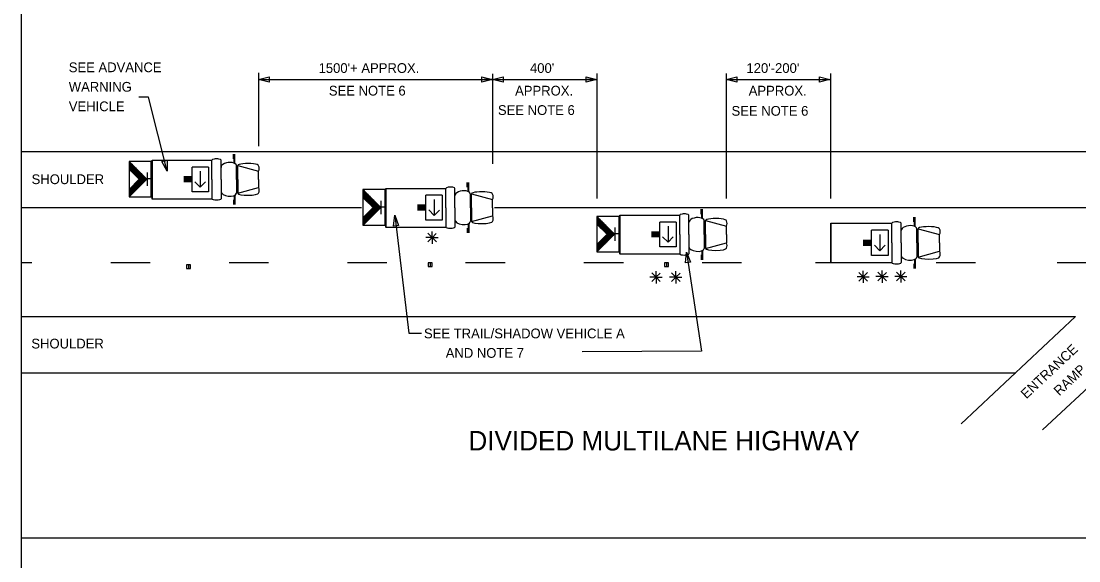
# Model space of a CAD drawing. Extents: x 1807779 to 1818251, y 673292 to 678849.
# Drawn here: x 1816601 to 1817251, y 676712 to 677044 of the extents above; entities that cross this region are included whole.
import ezdxf

# ---------------------------------------------------------------- set-up
doc = ezdxf.new("R2010")
doc.units = 0
for name, color, linetype in [('DSN_DRFT_Guideline-No-Plot', 7, 'Continuous'), ('DSN_RDWY_Drive', 7, 'Continuous'), ('Level 1', 7, 'Continuous')]:
    doc.layers.add(name, color=color, linetype=linetype)

msp = doc.modelspace()

# ---------------------------------------------------------------- linework, layer by layer
at = {"layer": 'DSN_DRFT_Guideline-No-Plot'}
msp.add_lwpolyline([(1816600.63, 676379.88), (1818250.63, 676379.88), (1818250.63, 677429.88), (1816600.63, 677429.88)], close=True, dxfattribs=at)
at = {"layer": 'DSN_RDWY_Drive'}
for p, q in [((1816746.7, 677012.14), (1816746.7, 676967.16)), ((1816746.7, 677008.08), (1816752.26, 677008.08)), ((1816746.7, 677008.08), (1816890.57, 677008.08)), ((1816890.57, 677008.08), (1816885.28, 677008.08)), ((1816890.57, 677011.54), (1816890.57, 676956.09)), ((1816890.57, 677008.08), (1816896.75, 677008.08)), ((1816890.57, 677008.08), (1816954.71, 677008.08)), ((1816953.98, 677008.08), (1816948.69, 677008.08)), ((1816954.71, 677011.78), (1816954.71, 676934.89)), ((1817034.25, 677011.78), (1817034.25, 676934.89)), ((1817034.25, 677008.08), (1817040.43, 677008.08)), ((1817034.25, 677008.08), (1817098.39, 677008.08)), ((1817098.39, 677011.78), (1817098.39, 676934.89)), ((1816600.9, 676963.87), (1817400.95, 676963.87)), ((1816731.21, 676959.21), (1816731.21, 676962.12)), ((1816731.67, 676956.41), (1816731.67, 676962.12)), ((1816732.06, 676956.41), (1816732.06, 676962.12)), ((1816666.98, 676957.72), (1816677.93, 676946.78)), ((1816681.08, 676958.23), (1816681.08, 676934.46)), ((1816681.18, 676934.73), (1816681.18, 676958.5)), ((1816681.18, 676958.5), (1816681.18, 676934.73)), ((1816681.18, 676958.5), (1816717.97, 676958.5)), ((1816715.81, 676954.22), (1816705.76, 676954.22)), ((1816705.76, 676939), (1816705.76, 676954.22)), ((1816715.81, 676954.22), (1816715.81, 676939)), ((1816717.97, 676946.61), (1816717.97, 676958.5)), ((1816723.61, 676946.61), (1816723.61, 676958.5)), ((1816733.05, 676946.61), (1816733.05, 676955.17)), ((1816733.84, 676955.17), (1816746.7, 676951.66)), ((1816733.84, 676946.61), (1816733.84, 676955.17)), ((1816666.98, 676952.97), (1816673.26, 676946.71)), ((1816678.3, 676942.65), (1816678.3, 676950.9)), ((1816705.76, 676948.13), (1816700.63, 676948.13)), ((1816705.76, 676947.37), (1816700.63, 676947.37)), ((1816710.78, 676951.64), (1816710.78, 676941.9)), ((1816746.7, 676946.61), (1816746.7, 676951.66)), ((1816666.98, 676940.44), (1816673.26, 676946.71)), ((1816667.04, 676935.87), (1816677.93, 676946.78)), ((1816680.59, 676946.97), (1816678.24, 676946.97)), ((1816705.76, 676946.61), (1816700.63, 676946.61)), ((1816705.76, 676945.85), (1816700.63, 676945.85)), ((1816705.76, 676945.09), (1816700.63, 676945.09)), ((1816710.78, 676941.9), (1816707.48, 676945.21)), ((1816710.78, 676941.9), (1816714.01, 676945.13)), ((1816717.97, 676946.61), (1816717.97, 676934.73)), ((1816723.61, 676946.61), (1816723.61, 676934.73)), ((1816733.05, 676946.61), (1816733.05, 676938.05)), ((1816733.84, 676946.61), (1816733.84, 676938.05)), ((1816733.84, 676938.05), (1816746.7, 676941.57)), ((1816746.7, 676946.61), (1816746.7, 676941.57)), ((1816824.95, 676940.81), (1816824.95, 676917.04)), ((1816825.04, 676941.09), (1816825.04, 676917.32)), ((1816825.04, 676917.31), (1816825.04, 676941.08)), ((1816825.04, 676941.08), (1816861.84, 676941.08)), ((1816861.84, 676929.2), (1816861.84, 676941.08)), ((1816867.47, 676929.2), (1816867.47, 676941.08)), ((1816875.07, 676941.79), (1816875.07, 676944.7)), ((1816875.53, 676939), (1816875.53, 676944.7)), ((1816875.92, 676939), (1816875.92, 676944.7)), ((1816681.18, 676934.73), (1816717.97, 676934.73)), ((1816715.81, 676939), (1816705.76, 676939)), ((1816731.67, 676936.82), (1816731.67, 676931.11)), ((1816732.06, 676936.82), (1816732.06, 676931.11)), ((1816810.84, 676940.31), (1816821.8, 676929.36)), ((1816810.84, 676935.56), (1816817.12, 676929.29)), ((1816859.68, 676936.81), (1816849.62, 676936.81)), ((1816849.62, 676921.59), (1816849.62, 676936.81)), ((1816859.68, 676936.81), (1816859.68, 676921.59)), ((1816876.92, 676929.2), (1816876.92, 676937.76)), ((1816877.7, 676937.76), (1816890.57, 676934.24)), ((1816877.7, 676929.2), (1816877.7, 676937.76)), ((1816600.9, 676929.38), (1816747.16, 676929.38)), ((1816731.21, 676934.02), (1816731.21, 676931.11)), ((1816746.94, 676929.38), (1816809.89, 676929.38)), ((1816810.84, 676923.03), (1816817.12, 676929.29)), ((1816810.9, 676918.46), (1816821.8, 676929.36)), ((1816824.46, 676929.56), (1816822.1, 676929.56)), ((1816822.17, 676925.24), (1816822.17, 676933.48)), ((1816849.62, 676930.72), (1816844.5, 676930.72)), ((1816849.62, 676929.96), (1816844.5, 676929.96)), ((1816849.62, 676929.2), (1816844.5, 676929.2)), ((1816849.62, 676928.44), (1816844.5, 676928.44)), ((1816854.65, 676924.49), (1816851.34, 676927.8)), ((1816854.65, 676934.22), (1816854.65, 676924.49)), ((1816861.84, 676929.2), (1816861.84, 676917.32)), ((1816867.47, 676929.2), (1816867.47, 676917.32)), ((1816876.92, 676929.2), (1816876.92, 676920.64)), ((1816877.7, 676929.2), (1816877.7, 676920.64)), ((1816890.57, 676929.2), (1816890.57, 676934.24)), ((1816890.57, 676929.2), (1816890.57, 676924.16)), ((1816891.88, 676929.38), (1817400.95, 676929.38)), ((1817018.94, 676925.32), (1817018.94, 676928.23)), ((1817019.4, 676922.52), (1817019.4, 676928.23)), ((1817019.79, 676922.52), (1817019.79, 676928.23)), ((1816849.62, 676927.68), (1816844.5, 676927.68)), ((1816859.68, 676921.59), (1816849.62, 676921.59)), ((1816854.65, 676924.49), (1816857.88, 676927.72)), ((1816877.7, 676920.64), (1816890.57, 676924.16)), ((1816954.71, 676923.83), (1816965.66, 676912.89)), ((1816968.82, 676924.34), (1816968.82, 676900.57)), ((1816968.91, 676900.84), (1816968.91, 676924.61)), ((1816968.91, 676924.61), (1816968.91, 676900.84)), ((1816968.91, 676924.61), (1817005.7, 676924.61)), ((1817005.7, 676912.72), (1817005.7, 676924.61)), ((1817011.34, 676912.72), (1817011.34, 676924.61)), ((1817020.78, 676912.72), (1817020.78, 676921.28)), ((1817021.57, 676921.28), (1817034.43, 676917.77)), ((1817021.57, 676912.72), (1817021.57, 676921.28)), ((1817149.71, 676920.41), (1817149.71, 676923.38)), ((1817150.18, 676917.56), (1817150.18, 676923.38)), ((1817150.58, 676917.56), (1817150.58, 676923.38)), ((1816825.04, 676917.32), (1816861.84, 676917.32)), ((1816875.07, 676916.6), (1816875.07, 676913.7)), ((1816875.53, 676919.41), (1816875.53, 676913.7)), ((1816875.92, 676919.41), (1816875.92, 676913.7)), ((1816954.71, 676919.08), (1816960.99, 676912.82)), ((1816966.03, 676908.76), (1816966.03, 676917.01)), ((1817003.54, 676920.33), (1816993.49, 676920.33)), ((1816993.49, 676905.11), (1816993.49, 676920.33)), ((1816998.51, 676917.75), (1816998.51, 676908.01)), ((1817003.54, 676920.33), (1817003.54, 676905.11)), ((1817034.43, 676912.72), (1817034.43, 676917.77)), ((1817098.66, 676919.69), (1817136.2, 676919.69)), ((1817098.66, 676895.43), (1817098.66, 676919.69)), ((1817098.66, 676919.69), (1817098.66, 676895.44)), ((1817134, 676915.32), (1817123.74, 676915.32)), ((1817123.74, 676899.8), (1817123.74, 676915.32)), ((1817134, 676915.32), (1817134, 676899.8)), ((1817136.2, 676907.56), (1817136.2, 676919.69)), ((1817141.95, 676907.56), (1817141.95, 676919.69)), ((1817151.59, 676907.56), (1817151.59, 676916.3)), ((1817152.39, 676916.3), (1817165.52, 676912.71)), ((1817152.39, 676907.56), (1817152.39, 676916.3)), ((1816853.4, 676910.77), (1816849.64, 676910.77)), ((1816853.4, 676910.77), (1816850.74, 676913.43)), ((1816853.4, 676910.77), (1816850.74, 676908.11)), ((1816853.34, 676910.72), (1816856, 676913.38)), ((1816853.4, 676910.77), (1816853.4, 676914.53)), ((1816853.4, 676910.77), (1816856.06, 676908.11)), ((1816853.4, 676910.77), (1816853.4, 676907.01)), ((1816853.4, 676910.77), (1816857.16, 676910.77)), ((1816954.71, 676906.55), (1816960.99, 676912.82)), ((1816954.77, 676901.98), (1816965.66, 676912.89)), ((1816968.33, 676913.08), (1816965.97, 676913.08)), ((1816993.49, 676914.24), (1816988.36, 676914.24)), ((1816993.49, 676913.48), (1816988.36, 676913.48)), ((1816993.49, 676912.72), (1816988.36, 676912.72)), ((1816993.49, 676911.96), (1816988.36, 676911.96)), ((1816993.49, 676911.2), (1816988.36, 676911.2)), ((1816998.51, 676908.01), (1816995.21, 676911.32)), ((1816998.51, 676908.01), (1817001.74, 676911.24)), ((1817005.7, 676912.72), (1817005.7, 676900.84)), ((1817011.34, 676912.72), (1817011.34, 676900.84)), ((1817020.78, 676912.72), (1817020.78, 676904.16)), ((1817021.57, 676912.72), (1817021.57, 676904.16)), ((1817034.43, 676912.72), (1817034.43, 676907.68)), ((1817123.74, 676909.11), (1817118.51, 676909.11)), ((1817123.74, 676908.33), (1817118.51, 676908.33)), ((1817128.87, 676912.69), (1817128.87, 676902.76)), ((1817165.52, 676907.56), (1817165.52, 676912.71)), ((1817003.54, 676905.11), (1816993.49, 676905.11)), ((1817019.4, 676902.93), (1817019.4, 676897.22)), ((1817019.79, 676902.93), (1817019.79, 676897.22)), ((1817021.57, 676904.16), (1817034.43, 676907.68)), ((1817123.74, 676907.56), (1817118.51, 676907.56)), ((1817123.74, 676906.78), (1817118.51, 676906.78)), ((1817123.74, 676906.01), (1817118.51, 676906.01)), ((1817128.87, 676902.76), (1817125.49, 676906.13)), ((1817128.87, 676902.76), (1817132.16, 676906.05)), ((1817136.2, 676907.56), (1817136.2, 676895.44)), ((1817141.95, 676907.56), (1817141.95, 676895.44)), ((1817151.59, 676907.56), (1817151.59, 676898.83)), ((1817152.39, 676907.56), (1817152.39, 676898.83)), ((1817152.39, 676898.83), (1817165.52, 676902.42)), ((1817165.52, 676907.56), (1817165.52, 676902.42)), ((1816853.38, 676895.36), (1816850.95, 676895.36)), ((1816850.95, 676895.36), (1816850.95, 676892.93)), ((1816852.17, 676895.36), (1816852.17, 676892.93)), ((1816853.38, 676892.93), (1816853.38, 676895.36)), ((1816968.91, 676900.84), (1817005.7, 676900.84)), ((1816996.43, 676895.36), (1816996.42, 676892.93)), ((1816998.85, 676895.36), (1816996.43, 676895.36)), ((1816997.65, 676895.36), (1816997.64, 676892.93)), ((1816998.85, 676892.93), (1816998.85, 676895.36)), ((1817018.94, 676900.13), (1817018.94, 676897.22)), ((1817098.66, 676895.44), (1817136.2, 676895.44)), ((1817134, 676899.8), (1817123.74, 676899.8)), ((1817150.18, 676897.57), (1817150.18, 676891.74)), ((1817150.58, 676897.57), (1817150.58, 676891.74)), ((1816704.84, 676894.15), (1816702.41, 676894.15)), ((1816702.41, 676894.15), (1816702.41, 676891.72)), ((1816702.41, 676891.72), (1816704.84, 676891.72)), ((1816703.63, 676894.15), (1816703.62, 676891.72)), ((1816704.84, 676891.72), (1816704.84, 676894.15)), ((1816850.95, 676892.93), (1816853.38, 676892.93)), ((1816991.12, 676886.41), (1816988.46, 676889.07)), ((1816991.05, 676886.36), (1816993.72, 676889.02)), ((1816991.12, 676886.41), (1816991.12, 676890.17)), ((1816996.42, 676892.93), (1816998.85, 676892.93)), ((1817003.29, 676886.41), (1817000.63, 676889.07)), ((1817003.22, 676886.36), (1817005.89, 676889.02)), ((1817003.29, 676886.41), (1817003.29, 676890.17)), ((1817118.57, 676886.65), (1817115.91, 676889.31)), ((1817118.5, 676886.6), (1817121.17, 676889.26)), ((1817118.57, 676886.65), (1817118.57, 676890.41)), ((1817130.19, 676886.81), (1817127.53, 676889.47)), ((1817130.12, 676886.76), (1817132.79, 676889.42)), ((1817130.19, 676886.81), (1817130.19, 676890.57)), ((1817141.72, 676886.89), (1817139.06, 676889.55)), ((1817141.65, 676886.84), (1817144.32, 676889.5)), ((1817141.72, 676886.89), (1817141.72, 676890.65)), ((1817149.71, 676894.71), (1817149.71, 676891.74)), ((1816991.12, 676886.41), (1816987.35, 676886.41)), ((1816991.12, 676886.41), (1816988.46, 676883.75)), ((1816991.12, 676886.41), (1816993.78, 676883.75)), ((1816991.12, 676886.41), (1816991.12, 676882.65)), ((1816991.12, 676886.41), (1816994.88, 676886.41)), ((1817003.29, 676886.41), (1816999.52, 676886.41)), ((1817003.29, 676886.41), (1817000.63, 676883.75)), ((1817003.29, 676886.41), (1817005.95, 676883.75)), ((1817003.29, 676886.41), (1817003.29, 676882.65)), ((1817003.29, 676886.41), (1817007.05, 676886.41)), ((1817118.57, 676886.65), (1817114.8, 676886.65)), ((1817118.57, 676886.65), (1817115.91, 676883.99)), ((1817118.57, 676886.65), (1817121.23, 676883.99)), ((1817118.57, 676886.65), (1817118.57, 676882.89)), ((1817118.57, 676886.65), (1817122.33, 676886.65)), ((1817130.19, 676886.81), (1817126.42, 676886.81)), ((1817130.19, 676886.81), (1817127.53, 676884.15)), ((1817130.19, 676886.81), (1817132.85, 676884.15)), ((1817130.19, 676886.81), (1817130.19, 676883.05)), ((1817130.19, 676886.81), (1817133.95, 676886.81)), ((1817141.72, 676886.89), (1817137.95, 676886.89)), ((1817141.72, 676886.89), (1817139.06, 676884.23)), ((1817141.72, 676886.89), (1817144.38, 676884.23)), ((1817141.72, 676886.89), (1817141.72, 676883.13)), ((1817141.72, 676886.89), (1817145.48, 676886.89)), ((1816600.9, 676862.16), (1817249.24, 676862.16)), ((1817249.24, 676862.16), (1817178.72, 676796.21)), ((1817303.36, 676862.16), (1817228.88, 676792.52)), ((1816600.9, 676827.68), (1817212.37, 676827.68)), ((1816600.9, 676726), (1817400.35, 676726))]:
    msp.add_line(p, q, dxfattribs=at)
for points in [[(1816753.19, 677006.45), (1816746.69, 677008.08), (1816753.19, 677009.7)], [(1816884.07, 677009.7), (1816890.57, 677008.08), (1816884.07, 677006.45)], [(1816897.07, 677006.45), (1816890.57, 677008.08), (1816897.07, 677009.7)], [(1816948.21, 677009.7), (1816954.71, 677008.08), (1816948.21, 677006.45)], [(1817040.75, 677006.45), (1817034.25, 677008.08), (1817040.75, 677009.7)], [(1817091.62, 677009.7), (1817098.12, 677008.08), (1817091.62, 677006.45)], [(1816666.98, 676957.72), (1816666.98, 676935.87), (1816680.63, 676935.87), (1816680.63, 676957.72)], [(1816690.37, 676958.44), (1816690.4, 676951.74), (1816687.22, 676957.64)], [(1816810.84, 676940.31), (1816810.84, 676918.46), (1816824.5, 676918.46), (1816824.5, 676940.31)], [(1816829.6, 676917.9), (1816830.44, 676924.54), (1816832.82, 676918.28)], [(1816954.71, 676923.83), (1816954.71, 676901.98), (1816968.36, 676901.98), (1816968.36, 676923.83)], [(1817009.22, 676895.24), (1817009.85, 676901.91), (1817012.43, 676895.72)]]:
    msp.add_lwpolyline(points, close=True, dxfattribs=at)
for points in [[(1816690.4, 676951.74), (1816678.87, 676997.18), (1816673.1, 676997.18)], [(1816666.98, 676957.21), (1816672.76, 676947.2)], [(1816666.98, 676956.35), (1816671.61, 676948.31)], [(1816666.98, 676955.49), (1816670.47, 676949.44)], [(1816666.98, 676954.62), (1816669.32, 676950.56)], [(1816667.47, 676957.24), (1816675.12, 676943.97)], [(1816668.63, 676956.06), (1816675.43, 676944.29)], [(1816669.81, 676954.89), (1816675.75, 676944.6)], [(1816666.98, 676953.76), (1816668.18, 676951.68)], [(1816666.98, 676952.9), (1816667.04, 676952.81)], [(1816670.98, 676953.71), (1816676.07, 676944.91)], [(1816672.16, 676952.54), (1816676.38, 676945.23)], [(1816673.33, 676951.36), (1816676.71, 676945.53)], [(1816674.51, 676950.19), (1816677.03, 676945.82)], [(1816675.69, 676949.03), (1816677.32, 676946.19)], [(1816676.77, 676947.96), (1816677.61, 676946.49)], [(1816667.44, 676940.91), (1816669.12, 676937.99)], [(1816667.76, 676941.22), (1816669.43, 676938.31)], [(1816668.07, 676941.54), (1816669.75, 676938.62)], [(1816668.38, 676941.85), (1816670.06, 676938.94)], [(1816668.7, 676942.16), (1816670.38, 676939.25)], [(1816669.02, 676942.48), (1816670.7, 676939.57)], [(1816669.33, 676942.8), (1816671.01, 676939.88)], [(1816669.65, 676943.11), (1816671.33, 676940.19)], [(1816669.97, 676943.43), (1816671.65, 676940.51)], [(1816670.28, 676943.75), (1816671.96, 676940.83)], [(1816670.59, 676944.06), (1816672.27, 676941.14)], [(1816670.91, 676944.37), (1816672.6, 676941.45)], [(1816671.22, 676944.69), (1816672.91, 676941.77)], [(1816671.54, 676945), (1816673.22, 676942.09)], [(1816671.86, 676945.32), (1816673.54, 676942.4)], [(1816672.17, 676945.63), (1816673.86, 676942.72)], [(1816672.49, 676945.94), (1816674.17, 676943.03)], [(1816672.8, 676946.27), (1816674.49, 676943.35)], [(1816673.12, 676946.58), (1816674.81, 676943.66)], [(1816666.98, 676939.98), (1816668.49, 676937.37)], [(1816666.98, 676939.12), (1816668.17, 676937.05)], [(1816666.98, 676938.26), (1816667.85, 676936.74)], [(1816666.98, 676937.39), (1816667.54, 676936.43)], [(1816666.98, 676936.53), (1816667.22, 676936.12)], [(1816667.12, 676940.59), (1816668.8, 676937.69)], [(1816810.84, 676939.8), (1816816.62, 676929.78)], [(1816810.84, 676938.94), (1816815.48, 676930.9)], [(1816810.84, 676938.08), (1816814.34, 676932.02)], [(1816810.84, 676937.21), (1816813.19, 676933.15)], [(1816810.84, 676936.35), (1816812.05, 676934.27)], [(1816810.84, 676935.49), (1816810.9, 676935.39)], [(1816811.33, 676939.83), (1816818.98, 676926.56)], [(1816812.5, 676938.65), (1816819.3, 676926.87)], [(1816813.67, 676937.48), (1816819.62, 676927.19)], [(1816814.85, 676936.3), (1816819.93, 676927.5)], [(1816816.02, 676935.13), (1816820.25, 676927.82)], [(1816815.72, 676927.91), (1816817.41, 676924.99)], [(1816816.04, 676928.22), (1816817.72, 676925.31)], [(1816816.36, 676928.53), (1816818.04, 676925.61)], [(1816816.66, 676928.85), (1816818.36, 676925.93)], [(1816816.99, 676929.17), (1816818.67, 676926.25)], [(1816817.2, 676933.95), (1816820.57, 676928.11)], [(1816818.37, 676932.78), (1816820.9, 676928.41)], [(1816819.55, 676931.62), (1816821.19, 676928.78)], [(1816820.64, 676930.54), (1816821.48, 676929.08)], [(1816810.84, 676922.57), (1816812.35, 676919.96)], [(1816810.84, 676921.7), (1816812.03, 676919.64)], [(1816810.99, 676923.18), (1816812.67, 676920.28)], [(1816811.31, 676923.5), (1816812.98, 676920.58)], [(1816811.62, 676923.81), (1816813.29, 676920.9)], [(1816811.94, 676924.13), (1816813.62, 676921.21)], [(1816812.25, 676924.44), (1816813.93, 676921.53)], [(1816812.57, 676924.75), (1816814.24, 676921.84)], [(1816812.88, 676925.07), (1816814.56, 676922.16)], [(1816813.2, 676925.38), (1816814.88, 676922.47)], [(1816813.52, 676925.7), (1816815.19, 676922.78)], [(1816813.83, 676926.02), (1816815.51, 676923.1)], [(1816814.15, 676926.33), (1816815.83, 676923.41)], [(1816814.45, 676926.64), (1816816.14, 676923.73)], [(1816814.78, 676926.96), (1816816.46, 676924.04)], [(1816815.09, 676927.28), (1816816.77, 676924.36)], [(1816815.4, 676927.58), (1816817.09, 676924.67)], [(1816830.44, 676924.54), (1816839.07, 676851.95), (1816846.98, 676851.95)], [(1816954.71, 676923.32), (1816960.49, 676913.31)], [(1816954.71, 676922.46), (1816959.34, 676914.42)], [(1816954.71, 676921.6), (1816958.2, 676915.55)], [(1816955.2, 676923.35), (1816962.85, 676910.08)], [(1816956.36, 676922.17), (1816963.17, 676910.4)], [(1816810.84, 676920.85), (1816811.72, 676919.33)], [(1816810.84, 676919.98), (1816811.41, 676919.01)], [(1816810.84, 676919.12), (1816811.08, 676918.71)], [(1816954.71, 676920.73), (1816957.06, 676916.67)], [(1816954.71, 676919.87), (1816955.91, 676917.79)], [(1816954.71, 676919.01), (1816954.77, 676918.92)], [(1816957.54, 676921), (1816963.48, 676910.71)], [(1816958.72, 676919.82), (1816963.8, 676911.02)], [(1816959.89, 676918.65), (1816964.11, 676911.34)], [(1816961.06, 676917.47), (1816964.44, 676911.64)], [(1816962.24, 676916.3), (1816964.76, 676911.93)], [(1816963.42, 676915.14), (1816965.05, 676912.3)], [(1816956.43, 676908.27), (1816958.11, 676905.36)], [(1816956.75, 676908.59), (1816958.43, 676905.68)], [(1816957.07, 676908.91), (1816958.75, 676905.99)], [(1816957.38, 676909.22), (1816959.06, 676906.3)], [(1816957.7, 676909.54), (1816959.38, 676906.62)], [(1816958.01, 676909.86), (1816959.69, 676906.94)], [(1816958.32, 676910.17), (1816960.01, 676907.25)], [(1816958.64, 676910.48), (1816960.33, 676907.56)], [(1816958.96, 676910.8), (1816960.64, 676907.88)], [(1816959.27, 676911.11), (1816960.96, 676908.2)], [(1816959.59, 676911.43), (1816961.27, 676908.51)], [(1816959.9, 676911.74), (1816961.59, 676908.83)], [(1816960.22, 676912.05), (1816961.9, 676909.14)], [(1816960.53, 676912.38), (1816962.22, 676909.46)], [(1816960.85, 676912.69), (1816962.54, 676909.77)], [(1816964.5, 676914.07), (1816965.35, 676912.6)], [(1816954.71, 676906.09), (1816956.22, 676903.48)], [(1816954.71, 676905.23), (1816955.9, 676903.16)], [(1816954.71, 676904.37), (1816955.59, 676902.85)], [(1816954.71, 676903.5), (1816955.27, 676902.54)], [(1816954.71, 676902.64), (1816954.95, 676902.23)], [(1816954.86, 676906.7), (1816956.53, 676903.8)], [(1816955.17, 676907.02), (1816956.85, 676904.1)], [(1816955.49, 676907.33), (1816957.16, 676904.42)], [(1816955.81, 676907.65), (1816957.48, 676904.73)], [(1816956.11, 676907.96), (1816957.8, 676905.05)], [(1816600.9, 676895.39), (1816607.26, 676895.39)], [(1816655.76, 676895.39), (1816680.02, 676895.39)], [(1816728.52, 676895.39), (1816752.77, 676895.39)], [(1816801.27, 676895.39), (1816825.52, 676895.39)], [(1816874.02, 676895.39), (1816898.28, 676895.39)], [(1816946.78, 676895.39), (1816971.03, 676895.39)], [(1817019.53, 676895.39), (1817043.79, 676895.39)], [(1817089.28, 676895.39), (1817113.54, 676895.39)], [(1817163.36, 676895.39), (1817187.61, 676895.39)], [(1817237.8, 676895.39), (1817262.05, 676895.39)]]:
    msp.add_lwpolyline(points, dxfattribs=at)
for centre, radius, start, end in [((1816743.55, 676953.34), 3.57, 331.88006, 28.11991), ((1816743.55, 676939.89), 3.57, 331.88008, 28.11994), ((1816887.42, 676935.93), 3.57, 331.88006, 28.11991), ((1816887.42, 676922.48), 3.57, 331.88008, 28.11994), ((1817031.28, 676919.45), 3.57, 331.88006, 28.11991), ((1817162.31, 676914.43), 3.64, 331.88006, 28.11991), ((1817031.28, 676906), 3.57, 331.88008, 28.11994), ((1817162.31, 676900.7), 3.64, 331.88008, 28.11994)]:
    msp.add_arc(centre, radius, start, end, dxfattribs=at)
for centre, major_axis, ratio, start_param, end_param in [((1816720.79, 676958.5), (2.82, 0), 0.269913, 0, 3.141593), ((1816728.33, 676954.59), (4.72, 0.58), 0.503092, 0, 3.141593), ((1816740.27, 676955.1), (6.43, -0.07), 0.2034, 0, 3.141593), ((1816864.65, 676941.08), (2.82, 0), 0.269913, 0, 3.141593), ((1816720.79, 676934.73), (2.82, 0), 0.269913, 3.141593, 6.283185), ((1816728.33, 676938.64), (4.72, -0.58), 0.503092, 3.141593, 6.283185), ((1816740.27, 676938.13), (6.43, 0.07), 0.2034, 3.141593, 6.283185), ((1816872.19, 676937.18), (4.72, 0.58), 0.503092, 0, 3.141593), ((1816884.13, 676937.69), (6.43, -0.07), 0.2034, 0, 3.141593), ((1816872.19, 676921.23), (4.72, -0.58), 0.503092, 3.141593, 6.283185), ((1817008.52, 676924.61), (2.82, 0), 0.269913, 0, 3.141593), ((1817016.06, 676920.7), (4.72, 0.58), 0.503092, 0, 3.141593), ((1817028, 676921.21), (6.43, -0.07), 0.2034, 0, 3.141593), ((1816864.65, 676917.32), (2.82, 0), 0.269913, 3.141593, 6.283185), ((1816884.13, 676920.71), (6.43, 0.07), 0.2034, 3.141593, 6.283185), ((1817139.08, 676919.69), (2.88, 0), 0.269913, 0, 3.141593), ((1817146.77, 676915.7), (4.82, 0.6), 0.503092, 0, 3.141593), ((1817158.96, 676916.22), (6.56, -0.08), 0.2034, 0, 3.141593), ((1817016.06, 676904.75), (4.72, -0.58), 0.503092, 3.141593, 6.283185), ((1817028, 676904.24), (6.43, 0.07), 0.2034, 3.141593, 6.283185), ((1817008.52, 676900.84), (2.82, 0), 0.269913, 3.141593, 6.283185), ((1817139.08, 676895.44), (2.88, 0), 0.269913, 3.141593, 6.283185), ((1817146.77, 676899.42), (4.82, -0.6), 0.503092, 3.141593, 6.283185), ((1817158.96, 676898.9), (6.56, 0.08), 0.2034, 3.141593, 6.283185)]:
    msp.add_ellipse(centre, major_axis=major_axis, ratio=ratio, start_param=start_param, end_param=end_param, dxfattribs=at)
at = {"layer": 'Level 1'}
msp.add_lwpolyline([(1817009.85, 676901.91), (1817019.05, 676840.86), (1816945.77, 676840.58)], dxfattribs=at)

# ---------------------------------------------------------------- texts
at = {"layer": 'DSN_RDWY_Drive'}
for s, p in [('SEE ADVANCE ', (1816629.92, 677012.57)), ("1500'+ APPROX.", (1816783.58, 677012.11)), ("400'", (1816913.61, 677012.11)), ("120'-200'", (1817046.76, 677012.11)), ('WARNING ', (1816629.92, 677000.57)), ('SEE NOTE 6', (1816789.89, 676998.2)), ('APPROX.', (1816904.45, 676998.2)), ('APPROX.', (1817048.13, 676998.2)), ('VEHICLE', (1816629.92, 676988.57)), ('SEE NOTE 6', (1816893.89, 676986.26)), ('SEE NOTE 6', (1817037.57, 676985.78)), ('SEE TRAIL/SHADOW VEHICLE A ', (1816848.4, 676848.84)), ('      AND NOTE 7', (1816848.4, 676836.84))]:
    msp.add_text(s, height=6, dxfattribs=at).set_placement(p)
for s, height, rotation, p in [('SHOULDER', 6, 0, (1816607.07, 676943.71)), ('SHOULDER', 6, 0, (1816606.91, 676842.59)), ('ENTRANCE', 6, 43.07908, (1817218.91, 676811.27)), ('RAMP', 6, 43.07908, (1817239.16, 676813.12)), ('DIVIDED MULTILANE HIGHWAY', 12, 0, (1816875.74, 676779.84))]:
    msp.add_text(s, height=height, rotation=rotation, dxfattribs=at).set_placement(p)

doc.saveas('drawing.dxf')
